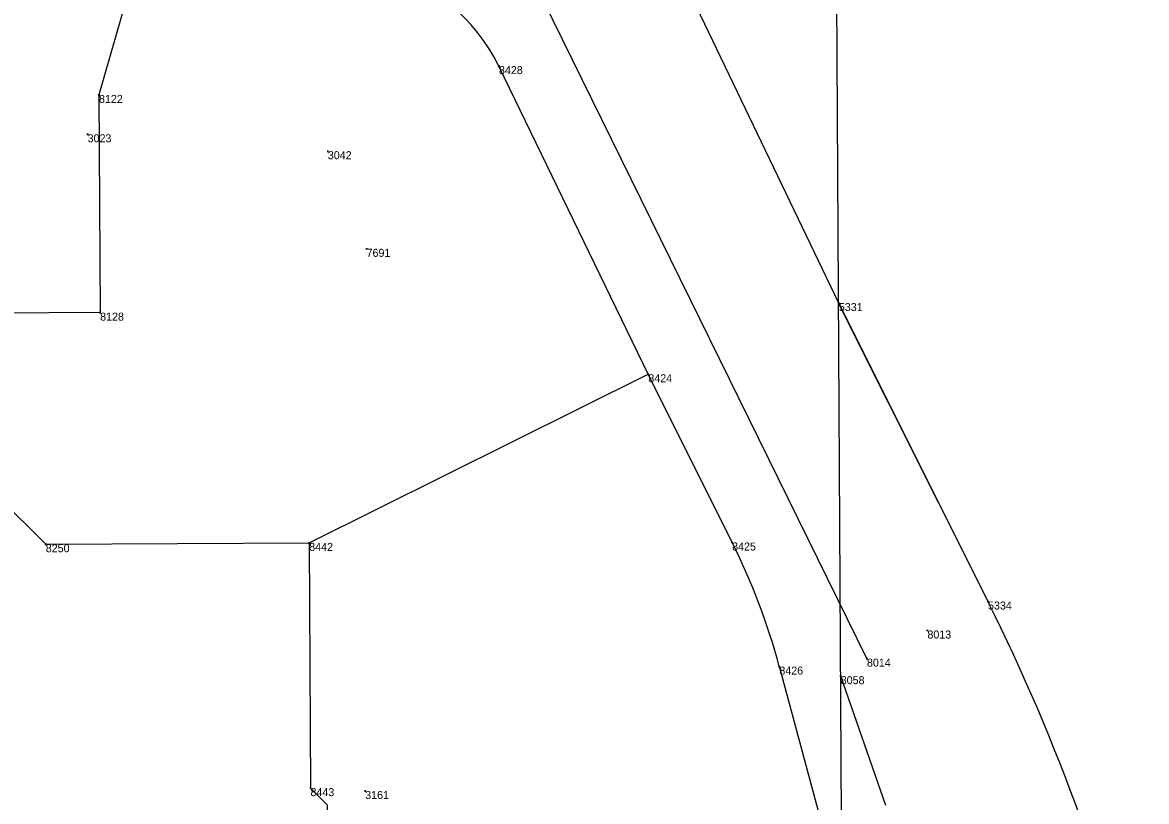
# Model space of a CAD drawing. Extents: x 2145146 to 2158053, y 137507 to 150829.
# Drawn here: x 2152334 to 2154019, y 144448 to 145617 of the extents above; entities that cross this region are included whole.
import ezdxf

# ---------------------------------------------------------------- set-up
doc = ezdxf.new("R2010")
doc.units = 0
for name, color, linetype in [('ALIGN_Cogo Points', 7, 'Continuous'), ('ALIGN_ROW Line', 7, 'Continuous'), ('PLSS_Property Line', 7, 'Continuous'), ('PLSS_Section Line', 7, 'Continuous')]:
    doc.layers.add(name, color=color, linetype=linetype)

msp = doc.modelspace()

# ---------------------------------------------------------------- linework, layer by layer
at = {"layer": 'ALIGN_Cogo Points'}
for points in [[(2153048.3, 145551.2), (2153048.3, 145552.4), (2153048.3, 145551.2), (2153047.1, 145551.2), (2153048.3, 145551.2), (2153048.3, 145550), (2153048.3, 145551.2), (2153049.5, 145551.2)], [(2152448.8, 145508), (2152448.8, 145509.2), (2152448.8, 145508), (2152447.6, 145508), (2152448.8, 145508), (2152448.8, 145506.8), (2152448.8, 145508), (2152450, 145508)], [(2152431.8, 145449), (2152431.8, 145450.2), (2152431.8, 145449), (2152430.6, 145449), (2152431.8, 145449), (2152431.8, 145447.8), (2152431.8, 145449), (2152433, 145449)], [(2152791.8, 145423.6), (2152791.8, 145424.8), (2152791.8, 145423.6), (2152790.6, 145423.6), (2152791.8, 145423.6), (2152791.8, 145422.4), (2152791.8, 145423.6), (2152793, 145423.6)], [(2152849.9, 145277.2), (2152849.9, 145278.4), (2152849.9, 145277.2), (2152848.7, 145277.2), (2152849.9, 145277.2), (2152849.9, 145276), (2152849.9, 145277.2), (2152851.1, 145277.2)], [(2152450.5, 145181.5), (2152450.5, 145182.7), (2152450.5, 145181.5), (2152449.3, 145181.5), (2152450.5, 145181.5), (2152450.5, 145180.3), (2152450.5, 145181.5), (2152451.7, 145181.5)], [(2153557.8, 145195.9), (2153557.8, 145197.1), (2153557.8, 145195.9), (2153556.6, 145195.9), (2153557.8, 145195.9), (2153557.8, 145194.7), (2153557.8, 145195.9), (2153559, 145195.9)], [(2153272.2, 145089.1), (2153272.2, 145090.3), (2153272.2, 145089.1), (2153271, 145089.1), (2153272.2, 145089.1), (2153272.2, 145087.9), (2153272.2, 145089.1), (2153273.4, 145089.1)], [(2152369, 144834.2), (2152369, 144835.4), (2152369, 144834.2), (2152367.8, 144834.2), (2152369, 144834.2), (2152369, 144833), (2152369, 144834.2), (2152370.2, 144834.2)], [(2152763.9, 144836.2), (2152763.9, 144837.4), (2152763.9, 144836.2), (2152762.7, 144836.2), (2152763.9, 144836.2), (2152763.9, 144835), (2152763.9, 144836.2), (2152765.1, 144836.2)], [(2153397.8, 144836.8), (2153397.8, 144838), (2153397.8, 144836.8), (2153396.6, 144836.8), (2153397.8, 144836.8), (2153397.8, 144835.6), (2153397.8, 144836.8), (2153399, 144836.8)], [(2153781.4, 144748.3), (2153781.4, 144749.5), (2153781.4, 144748.3), (2153780.2, 144748.3), (2153781.4, 144748.3), (2153781.4, 144747.1), (2153781.4, 144748.3), (2153782.6, 144748.3)], [(2153690.5, 144704.8), (2153690.5, 144706), (2153690.5, 144704.8), (2153689.3, 144704.8), (2153690.5, 144704.8), (2153690.5, 144703.6), (2153690.5, 144704.8), (2153691.7, 144704.8)], [(2153599.9, 144662.6), (2153599.9, 144663.8), (2153599.9, 144662.6), (2153598.7, 144662.6), (2153599.9, 144662.6), (2153599.9, 144661.4), (2153599.9, 144662.6), (2153601.1, 144662.6)], [(2153468.6, 144650.7), (2153468.6, 144651.9), (2153468.6, 144650.7), (2153467.4, 144650.7), (2153468.6, 144650.7), (2153468.6, 144649.5), (2153468.6, 144650.7), (2153469.8, 144650.7)], [(2153560.6, 144636.3), (2153560.6, 144637.5), (2153560.6, 144636.3), (2153559.4, 144636.3), (2153560.6, 144636.3), (2153560.6, 144635.1), (2153560.6, 144636.3), (2153561.8, 144636.3)], [(2152765.8, 144468.4), (2152765.8, 144469.6), (2152765.8, 144468.4), (2152764.6, 144468.4), (2152765.8, 144468.4), (2152765.8, 144467.2), (2152765.8, 144468.4), (2152767, 144468.4)], [(2152847.8, 144464.2), (2152847.8, 144465.4), (2152847.8, 144464.2), (2152846.6, 144464.2), (2152847.8, 144464.2), (2152847.8, 144463), (2152847.8, 144464.2), (2152849, 144464.2)]]:
    msp.add_lwpolyline(points, dxfattribs=at)
at = {"layer": 'ALIGN_ROW Line'}
for points in [[(2153599.9, 144662.6), (2153114.2, 145651.7)], [(2153781.4, 144748.3), (2153781.4, 144748.3), (2153557.8, 145195.9), (2153338.2, 145653)], [(2153782.4, 144746.2), (2153557.3, 145195.9)], [(2153628.3, 144442.3), (2153560.6, 144636.3)]]:
    msp.add_lwpolyline(points, dxfattribs=at)
msp.add_arc((2151128.8, 143423.6), 2964.9, 12.8977, 26.5388, dxfattribs=at)
at = {"layer": 'PLSS_Property Line'}
for points in [[(2152870.9, 145699), (2152870.9, 145699), (2152531.6, 145796.4), (2152448.8, 145508), (2152450.5, 145181.5), (2152296.2, 145180.7), (2152297.7, 144904.8), (2152369, 144834.2), (2152763.9, 144836.2), (2152765.8, 144468.4), (2152790.9, 144443.5), (2152791.4, 144359.7), (2152585.3, 144358.6), (2152560.2, 144383.4), (2152560, 144413.4), (2152243.4, 144411.8), (2152211, 144379), (2152211.5, 144277.6), (2152191.7, 144277.5), (2152193.9, 143760.5), (2152292.1, 143739.4), (2152358.2, 143726.6)], [(2153397.8, 144836.8), (2153397.8, 144836.8), (2153272.2, 145089.1), (2153048.3, 145551.2)], [(2152763.9, 144836.2), (2153272.2, 145089.1)], [(2153553.8, 144335.2), (2153553.8, 144335.2), (2153468.6, 144650.7), (2153468.6, 144650.7)]]:
    msp.add_lwpolyline(points, dxfattribs=at)
for centre, radius, start, end in [((2152791.8, 145423.6), 286.5, 26.4414, 73.9775), ((2152493, 144386.2), 1010.8, 15.1718, 26.4727)]:
    msp.add_arc(centre, radius, start, end, dxfattribs=at)
at = {"layer": 'PLSS_Section Line'}
msp.add_lwpolyline([(2153570, 143016.2), (2153554.7, 145654.3)], dxfattribs=at)

# ---------------------------------------------------------------- texts
at = {"layer": 'ALIGN_Cogo Points'}
for s, p in [('8428', (2153048.3, 145539.2)), ('8122', (2152448.8, 145496)), ('3023', (2152431.8, 145437)), ('3042', (2152791.8, 145411.6)), ('7691', (2152849.9, 145265.2)), ('5331', (2153557.8, 145183.9)), ('8128', (2152450.5, 145169.5)), ('8424', (2153272.2, 145077.1)), ('8250', (2152369, 144822.2)), ('8442', (2152763.9, 144824.2)), ('8425', (2153397.8, 144824.8)), ('5334', (2153781.4, 144736.3)), ('8013', (2153690.5, 144692.8)), ('8014', (2153599.9, 144650.6)), ('8426', (2153468.6, 144638.7)), ('8058', (2153560.6, 144624.3)), ('8443', (2152765.8, 144456.4)), ('3161', (2152847.8, 144452.2))]:
    msp.add_text(s, height=12, dxfattribs=at).set_placement(p)

doc.saveas('drawing.dxf')
